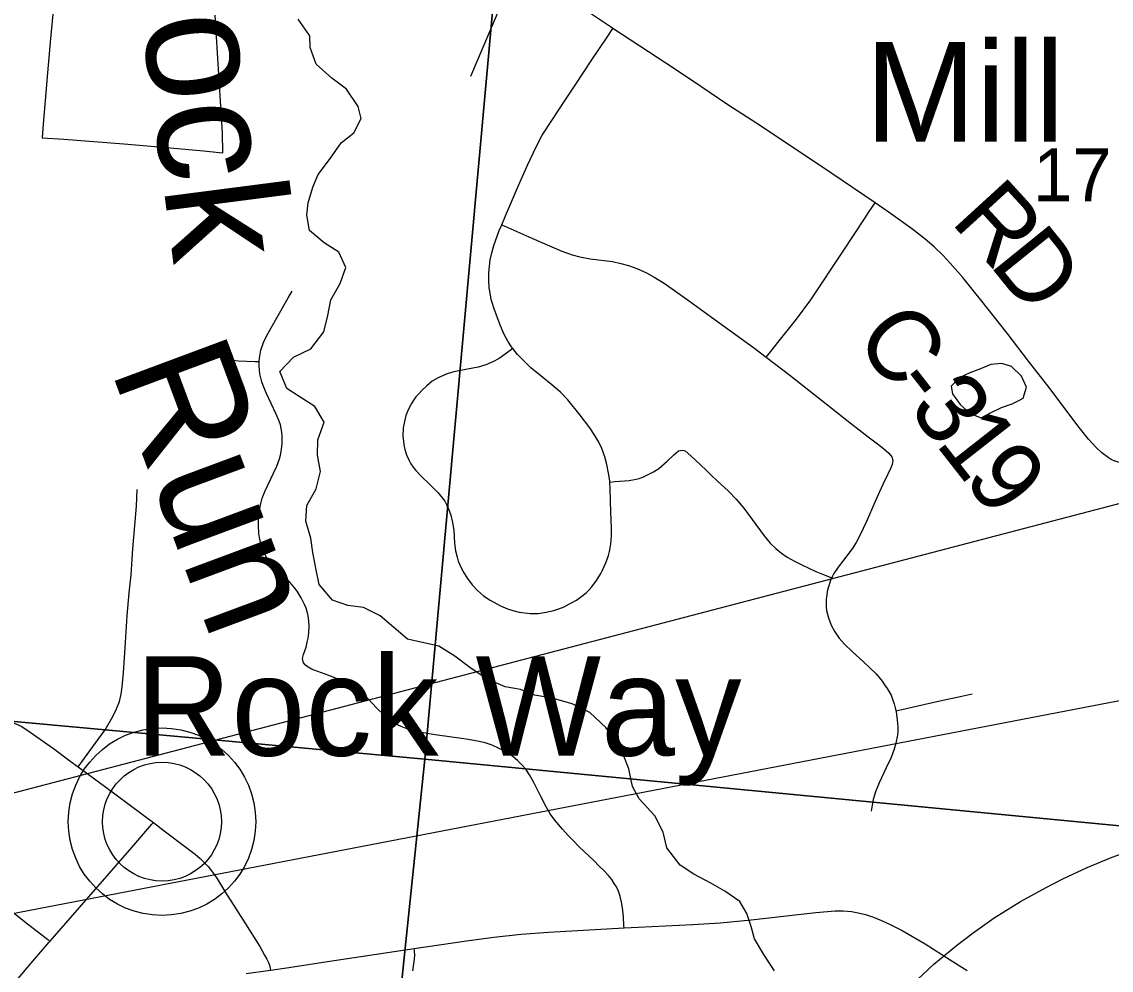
# Model space of a CAD drawing. Extents: x 0 to 34, y 0 to 22.
# Drawn here: x 5.672 to 6.536, y 19.65 to 20.403 of the extents above; entities that cross this region are included whole.
import ezdxf

# ---------------------------------------------------------------- set-up
doc = ezdxf.new("R2010")
doc.units = 0
for name, color, linetype in [('GM_X_Corporation', 7, 'Continuous'), ('GM_X_County_Road', 7, 'Continuous'), ('GM_X_County_Road_Text', 7, 'Continuous'), ('GM_X_Minor_Lake', 7, 'Continuous'), ('GM_X_Minor_River', 7, 'Continuous'), ('GM_X_Minor_River_Text', 7, 'Continuous'), ('GM_X_Rail_Line', 7, 'Continuous'), ('GM_X_Section_Text', 7, 'Continuous'), ('GM_X_Township_Road', 7, 'Continuous'), ('GM_X_Unincorporated', 7, 'Continuous'), ('GM_X_Unincorporated_Location', 7, 'Continuous'), ('GM_X_Unincorporated_Text', 7, 'Continuous'), ('GM_X_US_Route', 7, 'Continuous'), ('SH_Text', 7, 'Continuous')]:
    doc.layers.add(name, color=color, linetype=linetype)

msp = doc.modelspace()

# ---------------------------------------------------------------- linework, layer by layer
at = {"layer": 'GM_X_Corporation'}
for points in [[(5.03429, 20.91348), (6.08229, 20.82057), (5.99165, 19.81795), (4.9476, 19.91357)], [(6.08229, 20.82057), (7.08216, 20.72429), (6.98964, 19.72208), (5.99165, 19.81795)], [(4.9476, 19.91357), (5.99165, 19.81795), (5.88574, 18.80005), (4.86332, 18.87576)], [(5.99165, 19.81795), (6.98964, 19.72208), (6.90013, 18.71944), (5.88574, 18.80005)]]:
    msp.add_lwpolyline(points, close=True, dxfattribs=at)
at = {"layer": 'GM_X_County_Road'}
msp.add_line((5.77039, 19.7718), (5.7761, 19.76755), dxfattribs=at)
for points in [[(6.14067, 20.39807), (6.13895, 20.39921), (6.12053, 20.41138), (6.09916, 20.42552), (6.06825, 20.44607), (6.06527, 20.44806)], [(6.3489, 20.25943), (6.34068, 20.26508), (6.30647, 20.2884), (6.27655, 20.3083), (6.25798, 20.32063), (6.23214, 20.33743), (6.20389, 20.35631), (6.18268, 20.37044), (6.14067, 20.39807)], [(6.42813, 20.1884), (6.4186, 20.20029), (6.40857, 20.21163), (6.40256, 20.21814), (6.39579, 20.22461), (6.38871, 20.23073), (6.3789, 20.23841), (6.36115, 20.251), (6.3489, 20.25943)], [(6.65938, 20.07359), (6.64761, 20.07106), (6.59665, 20.06038), (6.5843, 20.05789), (6.57218, 20.05535), (6.56002, 20.05318), (6.55395, 20.0526), (6.54786, 20.05275), (6.54484, 20.05311), (6.54187, 20.05369), (6.53968, 20.05436), (6.53901, 20.05456), (6.53631, 20.05574), (6.53375, 20.05731), (6.52892, 20.06106), (6.52444, 20.06525), (6.51818, 20.07205), (6.50984, 20.08257), (6.48783, 20.11177), (6.47055, 20.13386), (6.45378, 20.15606), (6.43257, 20.18286), (6.42813, 20.1884)], [(5.65562, 19.84963), (5.65856, 19.84893), (5.66283, 19.84763), (5.66703, 19.84596), (5.67111, 19.84405), (5.6758, 19.84121), (5.69687, 19.82625), (5.70991, 19.81649), (5.71639, 19.81174)], [(5.71639, 19.81174), (5.73729, 19.79641), (5.76713, 19.77422), (5.77039, 19.7718)], [(5.7761, 19.76755), (5.78474, 19.76113), (5.8029, 19.74735), (5.80927, 19.74247), (5.81329, 19.73894), (5.81644, 19.73598), (5.81959, 19.73264), (5.82237, 19.72924), (5.82638, 19.7235), (5.83349, 19.71207), (5.84918, 19.68716), (5.86049, 19.66919), (5.86439, 19.66227), (5.86608, 19.65915), (5.86747, 19.65636), (5.86815, 19.65448), (5.86853, 19.653), (5.86915, 19.65047)]]:
    msp.add_lwpolyline(points, dxfattribs=at)
at = {"layer": 'GM_X_Minor_Lake'}
for points in [[(6.46395, 20.10324), (6.46637, 20.10449), (6.46909, 20.1132), (6.465, 20.12196), (6.45711, 20.12961), (6.44956, 20.13194), (6.44086, 20.13125), (6.43251, 20.12789), (6.42416, 20.12454), (6.41619, 20.1208), (6.40932, 20.11401)], [(6.40932, 20.11401), (6.41041, 20.10793), (6.4164, 20.09954), (6.42429, 20.09227), (6.43296, 20.08879), (6.44056, 20.09291), (6.44929, 20.09702), (6.45764, 20.09999), (6.46395, 20.10324)]]:
    msp.add_lwpolyline(points, dxfattribs=at)
at = {"layer": 'GM_X_Minor_River'}
for points in [[(5.97782, 19.9131), (5.96694, 19.92235), (5.95605, 19.9316), (5.94283, 19.93822), (5.93032, 19.93988), (5.91822, 19.94421), (5.90774, 19.95649), (5.90523, 19.96831), (5.90274, 19.98202), (5.90099, 19.99344), (5.89698, 20.00679), (5.8979, 20.01933), (5.90528, 20.03255), (5.90887, 20.04619), (5.90638, 20.05914), (5.90653, 20.0713), (5.91165, 20.08531), (5.90421, 20.09794), (5.89177, 20.10569), (5.88198, 20.11227), (5.87645, 20.12564), (5.88723, 20.13692), (5.90099, 20.1436), (5.91142, 20.15716), (5.91462, 20.17005), (5.91706, 20.18257), (5.92444, 20.19541), (5.92878, 20.20828), (5.92324, 20.22051), (5.91156, 20.22788), (5.8999, 20.23752), (5.89778, 20.24971), (5.89905, 20.25958), (5.90262, 20.27208), (5.90693, 20.28192), (5.91659, 20.29511), (5.9251, 20.30718), (5.93508, 20.31505), (5.94092, 20.32639), (5.93876, 20.33592), (5.92944, 20.34971), (5.91778, 20.3586), (5.90539, 20.36977), (5.90061, 20.38275), (5.90036, 20.39226), (5.89102, 20.4053)], [(6.26915, 19.64975), (6.26055, 19.66272), (6.25308, 19.67529), (6.25051, 19.68518), (6.24718, 19.69544), (6.24158, 19.70497), (6.22954, 19.71303), (6.21862, 19.71956), (6.20505, 19.72649), (6.19414, 19.73378), (6.18365, 19.74752), (6.18072, 19.76006), (6.17401, 19.77301), (6.16163, 19.78638), (6.15641, 19.79629), (6.15349, 19.81035), (6.14941, 19.82025), (6.1442, 19.83091), (6.13521, 19.84312), (6.12244, 19.85498), (6.1085, 19.86192), (6.09265, 19.86621), (6.07867, 19.86858), (6.06735, 19.87322), (6.05526, 19.87521), (6.04094, 19.88139), (6.02739, 19.8906), (6.01536, 19.89979), (6.00255, 19.90748), (5.97782, 19.9131)]]:
    msp.add_lwpolyline(points, dxfattribs=at)
at = {"layer": 'GM_X_Rail_Line'}
msp.add_lwpolyline([(6.37798, 19.6388), (6.39545, 19.65509), (6.41349, 19.67004), (6.4268, 19.68001), (6.44348, 19.69181), (6.46431, 19.70479), (6.4841, 19.7158), (6.49778, 19.72286), (6.51718, 19.73199), (6.53564, 19.73954), (6.55422, 19.74644)], dxfattribs=at)
at = {"layer": 'GM_X_Township_Road'}
for points in [[(6.06527, 20.44806), (6.0511, 20.41473), (6.02776, 20.35987)], [(5.69773, 20.42333), (5.69453, 20.38997), (5.69199, 20.36274), (5.69012, 20.34073), (5.68839, 20.31884), (5.68776, 20.31126), (5.70515, 20.31013), (5.75276, 20.3064), (5.78661, 20.30351), (5.81599, 20.3009), (5.82852, 20.29957), (5.83134, 20.29933), (5.83102, 20.31515), (5.82814, 20.36149), (5.82515, 20.40846)], [(6.05259, 20.24204), (6.05565, 20.24922), (6.06579, 20.27321), (6.07335, 20.29011), (6.07995, 20.30411), (6.08477, 20.31329), (6.09298, 20.32568), (6.10296, 20.34097), (6.11133, 20.35384), (6.12357, 20.37219), (6.13612, 20.39119), (6.14067, 20.39807)], [(6.26254, 20.13702), (6.26484, 20.13994), (6.27273, 20.14992), (6.28642, 20.16731), (6.29785, 20.18261), (6.32361, 20.22109), (6.34051, 20.24685), (6.34422, 20.2528), (6.3489, 20.25943)], [(6.04432, 20.18292), (6.04357, 20.18645), (6.04261, 20.19209), (6.04229, 20.19788), (6.04245, 20.20384), (6.04276, 20.20915), (6.04341, 20.2143), (6.0447, 20.21993), (6.04631, 20.22573), (6.05066, 20.23748), (6.05259, 20.24204)], [(6.05259, 20.24204), (6.0574, 20.23993), (6.07647, 20.23154), (6.10032, 20.22118), (6.10837, 20.21822), (6.11462, 20.21658), (6.12283, 20.2151), (6.14059, 20.21297), (6.14701, 20.21132), (6.15309, 20.20984), (6.15983, 20.20754), (6.16739, 20.20409), (6.17364, 20.20063), (6.18137, 20.1957), (6.20159, 20.1814), (6.21918, 20.16874), (6.25239, 20.14474), (6.26254, 20.13702)], [(5.86003, 20.13354), (5.86025, 20.13637), (5.86076, 20.1395), (5.86151, 20.1426), (5.86364, 20.14855), (5.86626, 20.15426), (5.88307, 20.18405), (5.88614, 20.18943)], [(6.06144, 20.14383), (6.06031, 20.14525), (6.05742, 20.14976), (6.05435, 20.15555), (6.05096, 20.16332), (6.04647, 20.17551), (6.0447, 20.18115), (6.04432, 20.18292)], [(6.06144, 20.14383), (6.05822, 20.14155), (6.05049, 20.13608), (6.0455, 20.13334), (6.03987, 20.13093), (6.03392, 20.129), (6.02538, 20.12739), (6.01444, 20.12529), (6.00929, 20.12384), (6.00559, 20.12224), (6.00156, 20.1203), (5.99738, 20.11789), (5.99303, 20.11435), (5.98949, 20.11081), (5.98677, 20.10783), (5.9845, 20.1055), (5.98273, 20.10308), (5.98096, 20.10018), (5.97855, 20.09584), (5.97645, 20.09085), (5.97533, 20.08602), (5.97436, 20.08087), (5.9742, 20.07443), (5.97453, 20.07041), (5.975, 20.06735), (5.97565, 20.06381), (5.97694, 20.05946), (5.97909, 20.0551), (5.98056, 20.05226), (5.98231, 20.0496), (5.98429, 20.04713), (5.98863, 20.04262), (5.99533, 20.03623), (6.00174, 20.02964), (6.00566, 20.02505), (6.00737, 20.02259), (6.00885, 20.02), (6.01013, 20.01728), (6.01123, 20.01447), (6.01217, 20.01161), (6.01355, 20.0057), (6.01448, 19.99963), (6.01508, 19.98945), (6.01589, 19.98317), (6.01718, 19.97814), (6.01813, 19.97512), (6.01931, 19.97221), (6.02208, 19.96663), (6.0254, 19.96132), (6.02922, 19.95637), (6.03347, 19.9518), (6.03579, 19.94965), (6.03823, 19.94767), (6.04344, 19.94417), (6.05157, 19.93955), (6.05725, 19.93714), (6.06127, 19.93585), (6.06643, 19.93461), (6.07515, 19.93354)], [(6.13832, 20.03788), (6.13826, 20.0388), (6.13734, 20.04503), (6.13596, 20.0519), (6.13435, 20.05802), (6.1321, 20.06445), (6.12968, 20.06961), (6.12646, 20.07476), (6.1226, 20.08087), (6.11487, 20.09101), (6.10506, 20.10308), (6.09926, 20.1092), (6.09244, 20.11502), (6.0852, 20.12096), (6.07577, 20.12867), (6.06932, 20.13479), (6.06514, 20.13914), (6.06144, 20.14383)], [(6.26254, 20.13702), (6.28116, 20.12287), (6.30631, 20.10298), (6.329, 20.08489), (6.34337, 20.07382), (6.3507, 20.06813), (6.35547, 20.06451), (6.35991, 20.06073), (6.36221, 20.05793), (6.36303, 20.0553), (6.36237, 20.05185), (6.36139, 20.04922), (6.35892, 20.04428), (6.35498, 20.03606), (6.34873, 20.02193), (6.34206, 20.00665), (6.33678, 19.99536), (6.33391, 19.98996), (6.3308, 19.98501), (6.31949, 19.97044), (6.31619, 19.9653), (6.31478, 19.9626), (6.31443, 19.9618)], [(5.83477, 20.13512), (5.84362, 20.13422), (5.85658, 20.13369), (5.86003, 20.13354)], [(6.14965, 19.68388), (6.14955, 19.68552), (6.14912, 19.69266), (6.1484, 19.69994), (6.14775, 19.70448), (6.14681, 19.70794), (6.14602, 19.71062), (6.14487, 19.71357), (6.14357, 19.71652), (6.14189, 19.71926), (6.13985, 19.72236), (6.13729, 19.72547), (6.13378, 19.7292), (6.12961, 19.73327), (6.12582, 19.73707), (6.12224, 19.74066), (6.11377, 19.7487), (6.10942, 19.75304), (6.10522, 19.7574), (6.10079, 19.76226), (6.09478, 19.76946), (6.09114, 19.77455), (6.08791, 19.77993), (6.08371, 19.7883), (6.07801, 19.79946), (6.07462, 19.80559), (6.07166, 19.81007), (6.06878, 19.81323), (6.06539, 19.8167), (6.06116, 19.82022), (6.05603, 19.82352), (6.05064, 19.82648), (6.04509, 19.829), (6.03932, 19.83091), (6.03337, 19.83232), (6.02426, 19.83384), (5.99972, 19.8371), (5.99056, 19.83872), (5.98447, 19.84008), (5.97844, 19.84179), (5.97553, 19.84277), (5.97266, 19.84391), (5.96985, 19.84525), (5.9671, 19.8468), (5.96447, 19.84857), (5.95959, 19.85257), (5.95283, 19.85902), (5.94651, 19.86585), (5.94221, 19.87021), (5.93993, 19.87221), (5.93752, 19.87405), (5.93499, 19.87572), (5.93235, 19.8772), (5.9268, 19.87979), (5.9153, 19.88431), (5.90361, 19.88852), (5.90155, 19.8894), (5.89902, 19.89091), (5.89685, 19.89264), (5.89526, 19.89445), (5.89456, 19.8978), (5.89515, 19.9011), (5.89728, 19.90684), (5.8983, 19.91067), (5.89895, 19.91406), (5.89952, 19.91824), (5.89974, 19.92379), (5.89959, 19.92783), (5.89909, 19.93158), (5.89821, 19.93521), (5.89733, 19.93781), (5.89611, 19.94068), (5.89337, 19.94604), (5.89185, 19.94865), (5.89018, 19.9512), (5.88838, 19.95366), (5.88442, 19.95831), (5.88008, 19.96256), (5.87546, 19.96671), (5.87319, 19.96888), (5.86898, 19.97364), (5.8671, 19.97623), (5.86541, 19.97894), (5.86392, 19.98175), (5.86267, 19.98468), (5.86169, 19.98771), (5.86031, 19.99387), (5.85983, 19.99699), (5.85942, 20.00329), (5.85963, 20.00958), (5.86034, 20.01582), (5.86157, 20.02201), (5.86246, 20.02505), (5.86474, 20.03089), (5.87142, 20.04497), (5.87401, 20.05057), (5.87618, 20.05628), (5.877, 20.05922), (5.87763, 20.0622), (5.87831, 20.06826), (5.87831, 20.07437), (5.87803, 20.0774), (5.87757, 20.08041), (5.87688, 20.08337), (5.87595, 20.08625), (5.87357, 20.09191), (5.86555, 20.10875), (5.86313, 20.11455), (5.86212, 20.11755), (5.86132, 20.12061), (5.8607, 20.12371), (5.86027, 20.12685), (5.86003, 20.13), (5.86002, 20.13137), (5.86003, 20.13354)], [(6.13832, 20.03788), (6.14239, 20.03822), (6.15365, 20.03913), (6.15921, 20.04013), (6.16176, 20.04083), (6.16446, 20.04181), (6.16729, 20.04304), (6.1729, 20.04591), (6.17716, 20.04852), (6.18392, 20.05448), (6.18923, 20.05963), (6.19278, 20.06268), (6.19599, 20.06317), (6.19825, 20.06268), (6.20259, 20.05882), (6.21026, 20.05156), (6.2147, 20.04729), (6.21915, 20.04309), (6.2236, 20.03895), (6.23245, 20.03057), (6.23864, 20.02438), (6.24477, 20.01729), (6.26086, 19.99508), (6.26569, 19.98945), (6.27003, 19.98511), (6.27454, 19.9814), (6.27921, 19.97818), (6.28484, 19.97496), (6.29063, 19.97207), (6.3019, 19.96692), (6.30979, 19.9637), (6.31443, 19.9618)], [(6.07515, 19.93354), (6.07836, 19.93341), (6.08153, 19.9336), (6.08776, 19.93448), (6.09396, 19.93595), (6.09721, 19.93701), (6.10209, 19.93892), (6.10647, 19.94122), (6.11198, 19.94422), (6.11727, 19.94808), (6.11972, 19.95014), (6.12196, 19.95242), (6.12401, 19.95483), (6.12777, 19.95984), (6.13116, 19.96517), (6.13261, 19.96799), (6.13514, 19.97372), (6.13729, 19.97961), (6.13813, 19.98266), (6.13875, 19.98576), (6.13918, 19.98889), (6.13966, 19.99517), (6.13974, 20.00143), (6.13928, 20.0139), (6.13869, 20.03254), (6.13832, 20.03788)], [(5.71639, 19.81174), (5.71731, 19.81299), (5.73001, 19.83024), (5.73776, 19.8412), (5.74404, 19.85188), (5.74685, 19.85777), (5.74925, 19.86365), (5.75059, 19.86952), (5.75139, 19.87527), (5.75233, 19.8865), (5.7538, 19.90628), (5.7554, 19.9318), (5.757, 19.94985), (5.75847, 19.96428), (5.75994, 19.98499), (5.76128, 20.00344), (5.76262, 20.01881), (5.76315, 20.03204)], [(6.31443, 19.9618), (6.31356, 19.95981), (6.31165, 19.95401), (6.31096, 19.95104), (6.31046, 19.94803), (6.31015, 19.945), (6.31002, 19.94196), (6.31011, 19.93892), (6.31044, 19.93591), (6.31105, 19.93295), (6.31186, 19.93003), (6.31406, 19.92434), (6.31688, 19.91891), (6.32045, 19.91391), (6.32472, 19.90914), (6.33081, 19.90339), (6.34002, 19.89501), (6.34971, 19.88564), (6.35448, 19.87971), (6.35646, 19.87692), (6.35859, 19.87396), (6.36155, 19.8687), (6.36299, 19.86485), (6.36407, 19.86185), (6.36491, 19.85878), (6.36538, 19.85633)], [(6.36538, 19.85633), (6.3701, 19.85736), (6.38293, 19.86015), (6.40035, 19.8641), (6.41646, 19.86755), (6.426, 19.86969)], [(6.36538, 19.85633), (6.3655, 19.85566), (6.36657, 19.84635), (6.3668, 19.84324), (6.36682, 19.84008), (6.36657, 19.83694), (6.36546, 19.83071), (6.36402, 19.82579), (6.36155, 19.81922), (6.35777, 19.811), (6.35218, 19.79899), (6.34922, 19.79193), (6.34742, 19.78601), (6.34659, 19.7814), (6.34589, 19.7766)], [(5.69405, 19.67323), (5.73027, 19.71472), (5.74671, 19.73358), (5.75893, 19.74782), (5.77013, 19.76083), (5.77499, 19.7663), (5.7761, 19.76755)], [(5.58648, 19.75739), (5.59105, 19.75378), (5.60076, 19.74611), (5.62008, 19.73078), (5.63721, 19.71762), (5.65681, 19.70259), (5.67616, 19.68723), (5.68757, 19.67842), (5.69227, 19.67466), (5.69405, 19.67323)], [(5.65483, 19.62051), (5.65682, 19.6261), (5.65845, 19.62959), (5.66102, 19.63414), (5.66884, 19.64386), (5.67895, 19.65578), (5.69326, 19.67233), (5.69405, 19.67323)], [(5.98197, 19.64981), (5.98338, 19.65907), (5.98363, 19.66225), (5.98335, 19.66542), (5.98316, 19.66757)]]:
    msp.add_lwpolyline(points, dxfattribs=at)
at = {"layer": 'GM_X_Unincorporated'}
for radius in [0.0744, 0.04716]:
    msp.add_circle((5.78301, 19.76828), radius, dxfattribs=at)
at = {"layer": 'GM_X_Unincorporated_Location'}
msp.add_line((5.78301, 19.76828), (5.78301, 19.76828), dxfattribs=at)
at = {"layer": 'GM_X_US_Route'}
msp.add_lwpolyline([(5.84979, 19.64766), (5.86915, 19.65047), (5.88357, 19.65256), (5.91422, 19.65717), (5.97253, 19.66601), (5.98316, 19.66757), (6.02473, 19.67369), (6.04629, 19.67658), (6.06792, 19.6789), (6.08961, 19.68057), (6.14965, 19.68388), (6.16089, 19.6845), (6.20426, 19.68667), (6.22593, 19.68808), (6.25062, 19.69035), (6.30173, 19.69621), (6.31717, 19.69755), (6.32343, 19.69755), (6.33005, 19.69695), (6.33557, 19.69596), (6.3412, 19.69461), (6.3477, 19.69241), (6.35395, 19.68984), (6.36082, 19.68677), (6.37026, 19.68199), (6.38852, 19.67132), (6.40838, 19.65869), (6.42199, 19.65024)], dxfattribs=at)
at = {"layer": 'SH_Text'}
msp.add_lwpolyline([(9.4782, 20.78964), (4.28936, 19.4307), (9.4782, 20.42968)], close=True, dxfattribs=at)

# ---------------------------------------------------------------- texts
at = {"layer": 'GM_X_County_Road_Text'}
for s, rotation, p in [('R', 312.44907, (6.40796, 20.24447)), ('D', 308.95338, (6.43886, 20.21073)), ('C', 307.84179, (6.33141, 20.15148)), ('-', 307.86995, (6.36006, 20.1146)), ('3', 307.90949, (6.37441, 20.09615)), ('1', 308.09641, (6.39604, 20.06837)), ('9', 308.66537, (6.41802, 20.04034))]:
    msp.add_text(s, height=0.05682, rotation=rotation, dxfattribs=at).set_placement(p)
at = {"layer": 'GM_X_Minor_River_Text'}
for s, height, rotation, p in [('Rock', 0.094801, 277.37265, (5.75509, 20.49662)), ('Run', 0.09476, 290.43216, (5.74187, 20.12795))]:
    msp.add_text(s, height=height, rotation=rotation, dxfattribs=at).set_placement(p)
at = {"layer": 'GM_X_Section_Text'}
msp.add_text('17', height=0.041856, rotation=0.00001, dxfattribs=at).set_placement((6.47429, 20.26087))
at = {"layer": 'GM_X_Unincorporated_Text'}
for s, p in [('Mill', (6.34096, 20.30816)), ('Rock Way', (5.76179, 19.82066))]:
    msp.add_text(s, height=0.078977, rotation=0.00001, dxfattribs=at).set_placement(p)

doc.saveas('drawing.dxf')
